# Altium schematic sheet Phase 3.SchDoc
size Tabloid; SheetNumber: 5; SheetTotal: 7
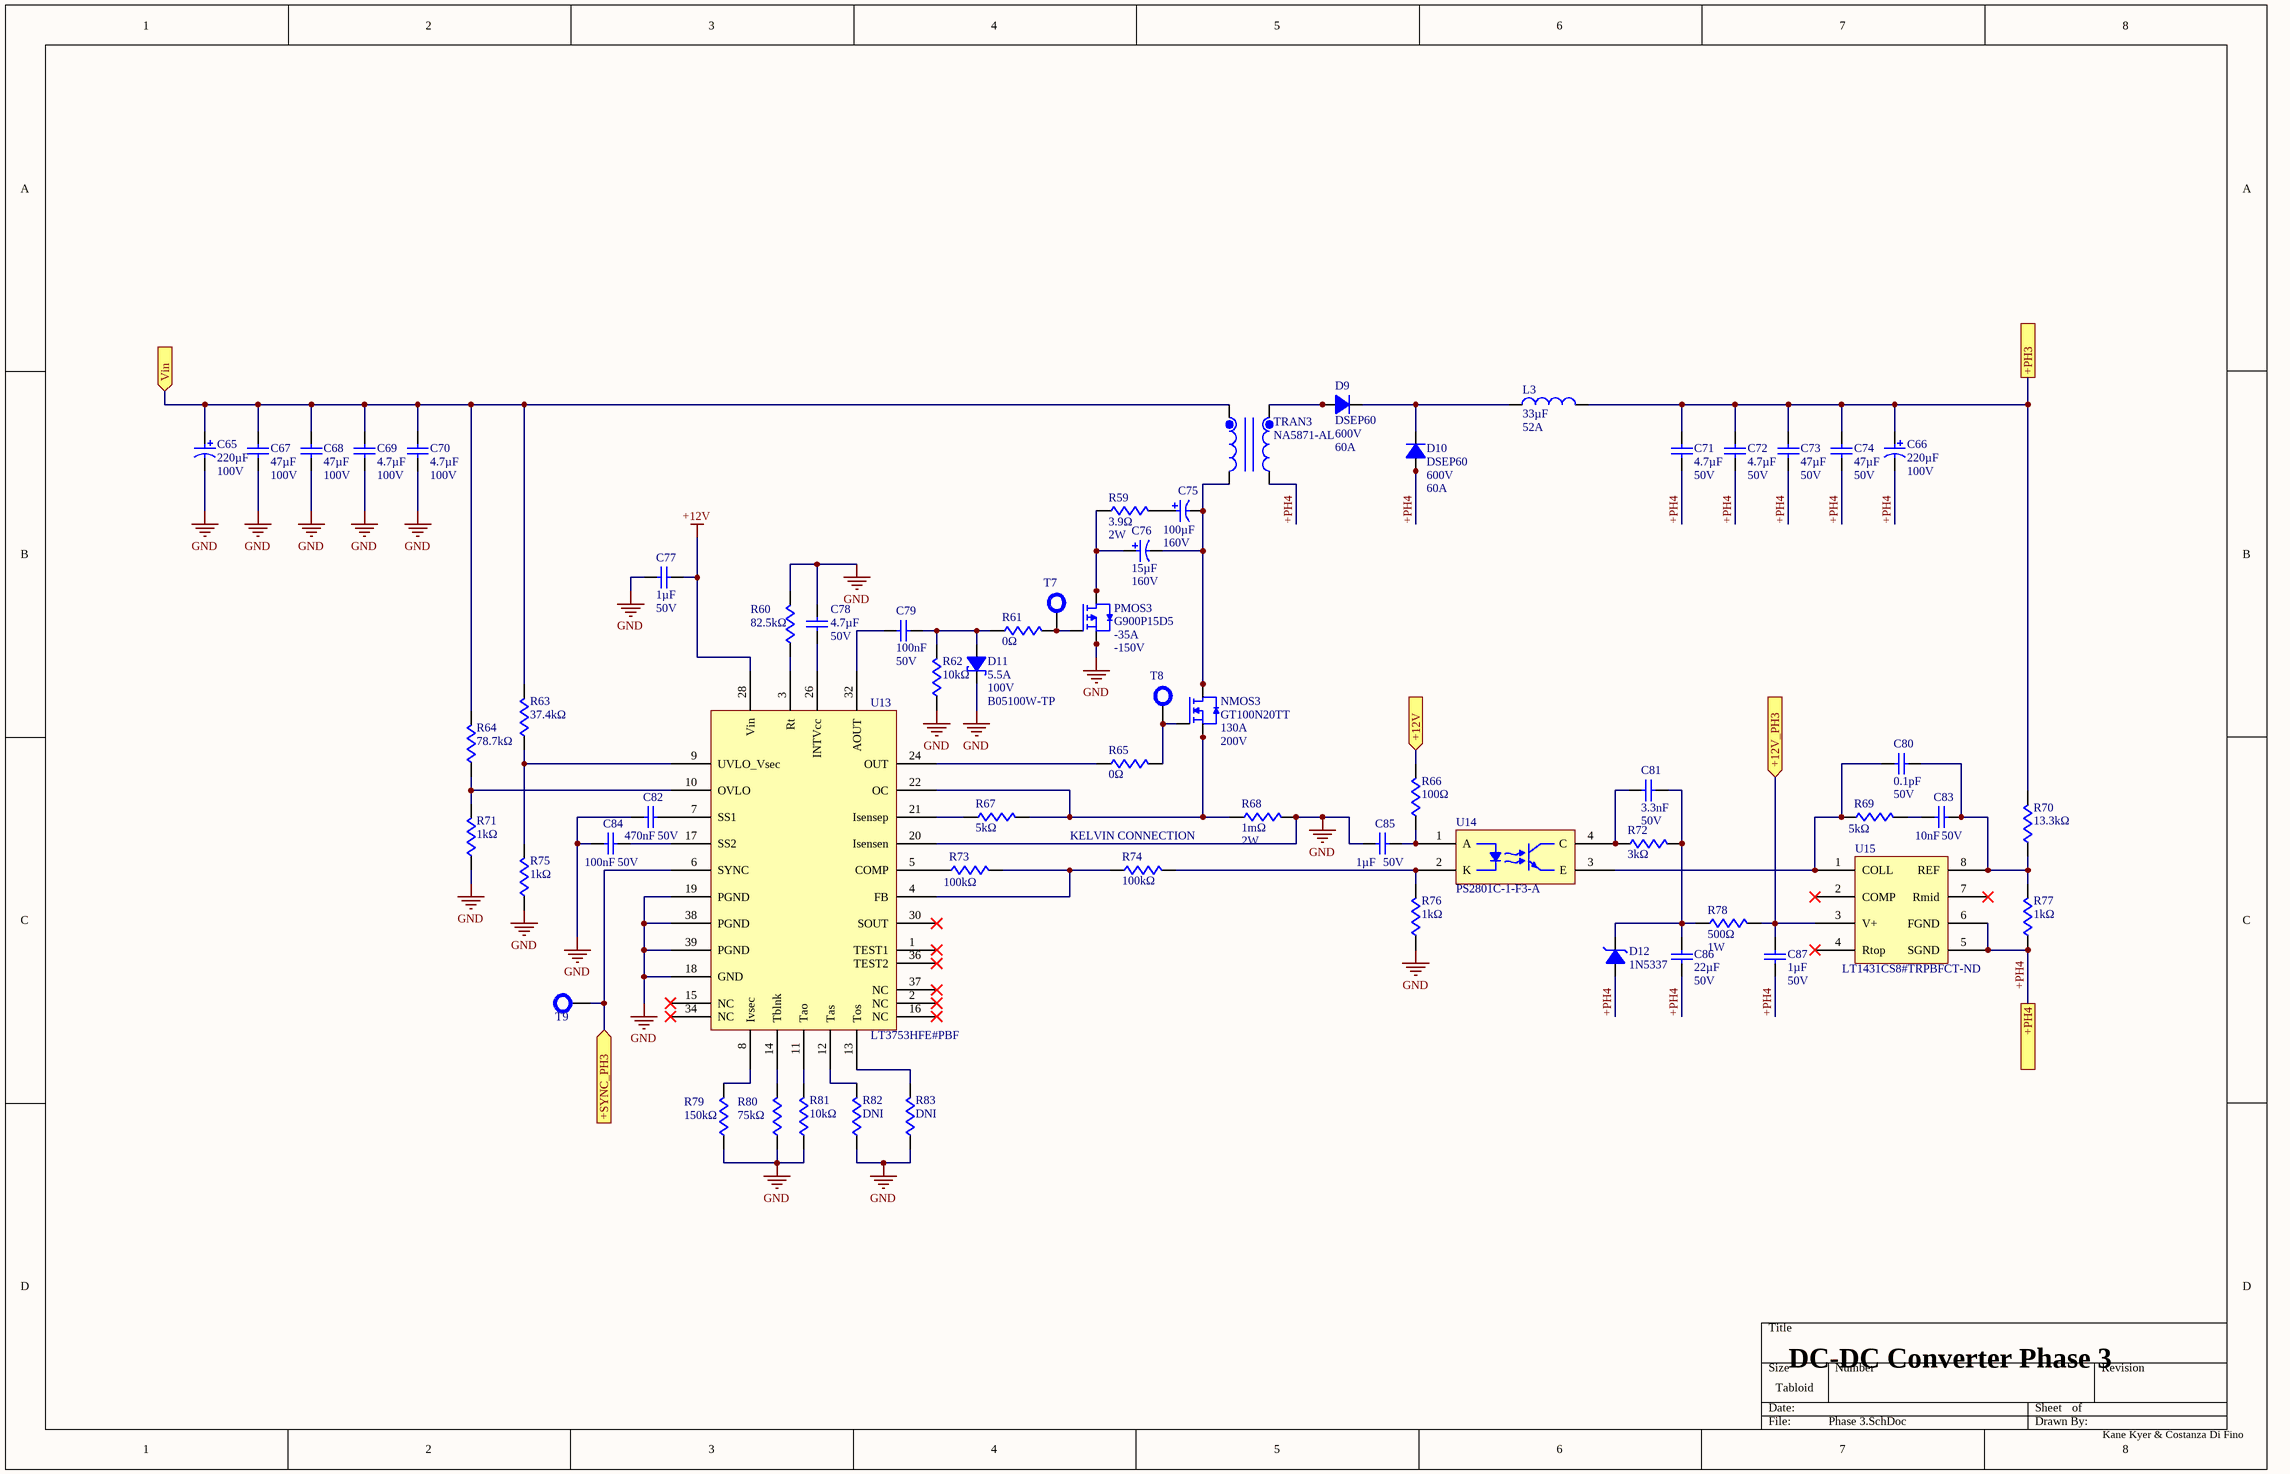
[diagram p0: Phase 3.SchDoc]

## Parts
C65  value 220µF  Voltage Rating: 100V  [C_AEC]  (hidden comment: AFK227M2AR44T-F)
C66  value 220µF  Voltage Rating: 100V  [C_AEC]  (hidden comment: AFK227M2AR44T-F)
C67  value 47µF  Voltage Rating: 100V  [C_CAA573]  (hidden comment: CAA573X7S2A476M640LH)
C68  value 47µF  Voltage Rating: 100V  [C_CAA573]  (hidden comment: CAA573X7S2A476M640LH)
C69  value 4.7µF  Voltage Rating (DC): 100V  [C_1210]  (hidden comment: GMC32X7S475K100NT)
C70  value 4.7µF  Voltage Rating (DC): 100V  [C_1210]  (hidden comment: GMC32X7S475K100NT)
C71  value 4.7µF  Voltage Rating (DC): 50V  [C_1206]  (hidden comment: GMC31X7R475K50NT)
C72  value 4.7µF  Voltage Rating (DC): 50V  [C_1206]  (hidden comment: GMC31X7R475K50NT)
C73  value 47µF  Voltage Rating (DC): 50V  [C_CKG57N]  (hidden comment: CKG57NX7R1H476M500JJ)
C74  value 47µF  Voltage Rating (DC): 50V  [C_CKG57N]  (hidden comment: CKG57NX7R1H476M500JJ)
C75  value 100µF  Voltage Rating (DC): 160V  [UUJ2C101MNJ1MS]  (hidden comment: UUJ2C101MNJ1MS)
C76  value 15µF  Voltage: 160V  [ULT2C150MNL1GS]  (hidden comment: ULT2C150MNL1GS)
C77  value 1µF  Voltage: 50V  [C_0805]  (hidden comment: CL21B105KBFNNNE)
C78  value 4.7µF  Voltage Rating (DC): 50V  [C_1206]  (hidden comment: GMC31X7R475K50NT)
C79  value 100nF  Voltage Rating: 50V  [C_0603]  (hidden comment: C0603C104K5RACTU)
C80  value 0.1pF  Voltage Rating: 50V  [C_0402]  (hidden comment: GJM1555C1HR10WB01D)
C81  value 3.3nF  Voltage Rating: 50V  [C_0603]  (hidden comment: GCM1885C1H332FA16D)
C82  value 470nF  Voltage Rating: 50V  [C_0402]  (hidden comment: GRM155R61H474KE11D)
C83  value 10nF  Voltage Rating: 50V  [C_0603]  (hidden comment: C0603C103K5RACTU)
C84  value 100nF  Voltage Rating: 50V  [C_0603]  (hidden comment: C0603C104K5RACTU)
C85  value 1µF  Voltage: 50V  [C_0805]  (hidden comment: CL21B105KBFNNNE)
C86  value 22µF  Voltage Rating (DC): 50V  [C_2220]  (hidden comment: GMC55X7R226M50NT)
C87  value 1µF  Voltage: 50V  [C_0805]  (hidden comment: CL21B105KBFNNNE)
D9  DSEP60  Vr: 600V  Io: 60A  [D_DSEP60]
D10  DSEP60  Vr: 600V  Io: 60A  [D_DSEP60]
D11  Max Forward Surge Current (Ifsm): 5.5A  Min Breakdown Voltage: 100V  [D_B05100W]  (hidden comment: B05100W-TP)
D12  Supplier Part Number: 1N5337  [D_1N5337]  (hidden comment: 1N5337BRLG)
L3  value 33µF  Irms: 52A  [CPEX4141L-330MC]  (hidden comment: CPEX4141L-330MC)
NMOS3  Id: 130A  Vds: 200V  [GT100N20TT]  (hidden comment: GT100N20TT)
PMOS3  Id: -35A  Vds: -150V  [G900P15]  (hidden comment: G900P15D5)
R59  value 3.9Ω  Power Rating: 2W  [R_SM2W]  (hidden comment: SMW23R9JT)
R60  value 82.5kΩ  [R_0805]  (hidden comment: RMCF0805FT82K5)
R61  value 0Ω  [R_0805]  (hidden comment: CRCW08050000Z0EA)
R62  value 10kΩ  [R_0402]  (hidden comment: RM04F1002CT)
R63  value 37.4kΩ  [R_0603]  (hidden comment: RC0603FR-0737K4L)
R64  value 78.7kΩ  [R_0603]  (hidden comment: RC0603FR-0778K7L)
R65  value 0Ω  [R_0805]  (hidden comment: CRCW08050000Z0EA)
R66  value 100Ω  [R_0603]  (hidden comment: RC0603FR-07100RL)
R67  value 5kΩ  [R_0402]  (hidden comment: PNM0402E5001BST1)
R68  value 1mΩ  Power Rating: 2W  [R_2512]  (hidden comment: CRE2512-FZ-R001E-2)
R69  value 5kΩ  [R_0402]  (hidden comment: PNM0402E5001BST1)
R70  value 13.3kΩ  [R_0603]  (hidden comment: RMCF0603FT13K3)
R71  value 1kΩ  [R_0402]  (hidden comment: RM04F1001CT)
R72  value 3kΩ  [C_0402]  (hidden comment: AC0402FR-073KL)
R73  value 100kΩ  [R_0402]  (hidden comment: RM04F1003CT)
R74  value 100kΩ  [R_0402]  (hidden comment: RM04F1003CT)
R75  value 1kΩ  [R_0402]  (hidden comment: RM04F1001CT)
R76  value 1kΩ  [R_0402]  (hidden comment: RM04F1001CT)
R77  value 1kΩ  [R_0402]  (hidden comment: RM04F1001CT)
R78  value 500Ω  Power Rating: 1W  [R_WSC2515]  (hidden comment: WSC2515500R0FEB)
R79  value 150kΩ  [R_0603]  (hidden comment: RC0603FR-07150KL)
R80  value 75kΩ  [R_0603]  (hidden comment: AC0603FR-0775KL)
R81  value 10kΩ  [R_0402]  (hidden comment: RM04F1002CT)
R82  value DNI  [R_0805]  (hidden comment: CRCW08050000Z0EA)
R83  value DNI  [R_0805]  (hidden comment: CRCW08050000Z0EA)
T7  TEST  [TEST_POINT]  (value not drawn)
T8  TEST  [TEST_POINT]  (value not drawn)
T9  TEST  [TEST_POINT]  (value not drawn)
TRAN3  NA5871-AL  [NA5871-AL]
U13  LT3753HFE#PBF  [LT3753]
U14  PS2801C-1-F3-A  [PS2801C]
U15  Supplier Part Number: LT1431CS8#TRPBFCT-ND  [LT1431]  (hidden comment: LT1431CS8#TRPBF)

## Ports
+12V (in, see SHEET_MAP[4C], Externals[2A], Phase 1[4C], Phase 2[4C], Phase 4[4C], Phase 5[4B]), +12V_PH3 (in, see SHEET_MAP[4C], Externals[6B]), +PH3 (see SHEET_MAP[4B], Externals[4C], Phase 2[6C]), +PH4 (see SHEET_MAP[4C], Externals[6B], Phase 4[6B]), +SYNC_PH3 (in, see SHEET_MAP[4C], Externals[3C]), Vin (in, see SHEET_MAP[4B], Externals[1A], Phase 1[1B], Phase 2[1B], Phase 4[1B], Phase 5[1B])

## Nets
+12V: C77.2 U13.28(Vin)
GND: C65.2 C67.1 C68.1 C69.1 C70.1 C77.1 C78.1 C82.1 C84.1 C85.1 D11.1 PMOS3.1(S) PMOS3.2(S) PMOS3.3(S) R60.2 R62.1 R68.2 R71.1 R75.1 R76.1 R79.1 R80.1 R81.1 R82.1 R83.1 U13.18(GND) U13.19(PGND) U13.20(Isensen) U13.38(PGND) U13.39(PGND)
+12V: R66.2 ; port +12V  [a separate net that carries the same name]
+12V_PH3: C87.2 R78.2 U15.3(V+) ; port +12V_PH3
+PH3: C66.1 C71.2 C72.2 C73.2 C74.2 L3.2 R70.2 ; port +PH3
+PH4: C66.2 C71.1 C72.1 C73.1 C74.1 C86.1 C87.1 D10.1(A) D10.3(A) D12.2 R77.1 TRAN3.11 U15.5(SGND) U15.6(FGND) ; port +PH4
+SYNC_PH3: T9.1 U13.6(SYNC) ; port +SYNC_PH3
Vin: C65.1 C67.2 C68.2 C69.2 C70.2 R63.2 R64.2 TRAN3.1 ; port Vin
NetC75_1: C75.1 R59.2
NetC75_2: C75.2 C76.2 NMOS3.9(D) NMOS3.10(D) NMOS3.11(D) NMOS3.12(D) NMOS3.13(D) NMOS3.14(D) NMOS3.15(D) NMOS3.16(D) TRAN3.4
NetC76_1: C76.1 PMOS3.5(D) PMOS3.6(D) PMOS3.7(D) PMOS3.8(D) R59.1
NetC78_2: C78.2 U13.26(INTVcc)
NetC79_1: C79.1 U13.32(AOUT)
NetC79_2: C79.2 D11.2 R61.1 R62.2
NetC80_1: C80.1 R69.1 U14.3(E) U15.1(COLL)
NetC80_2: C80.2 C83.2 R70.1 R77.2 U15.8(REF)
NetC81_1: C81.1 R72.1 U14.4(C)
NetC81_2: C81.2 C86.2 D12.1 R72.2 R78.1
NetC82_2: C82.2 U13.7(SS1)
NetC83_1: C83.1 R69.2
NetC84_2: C84.2 U13.17(SS2)
NetC85_2: C85.2 R66.1 U14.1(A)
NetD9_1: D9.1(A) D9.3(A) TRAN3.6
NetD9_4: D9.4(C) D10.4(C) L3.1
NetNMOS3_1: NMOS3.1(S) NMOS3.2(S) NMOS3.3(S) NMOS3.4(S) NMOS3.5(S) NMOS3.6(S) NMOS3.7(S) R67.2 R68.1 U13.22(OC)
NetNMOS3_8: NMOS3.8(G) R65.2 T8.1
NetPMOS3_4: PMOS3.4(G) R61.2 T7.1
NetR60_1: R60.1 U13.3(Rt)
NetR63_1: R63.1 R75.2 U13.9(UVLO_Vsec)
NetR64_1: R64.1 R71.2 U13.10(OVLO)
NetR65_1: R65.1 U13.24(OUT)
NetR67_1: R67.1 U13.21(Isensep)
NetR73_1: R73.1 U13.5(COMP)
NetR73_2: R73.2 R74.1 U13.4(FB)
NetR74_2: R74.2 R76.2 U14.2(K)
NetR79_2: R79.2 U13.8(Ivsec)
NetR80_2: R80.2 U13.14(Tblnk)
NetR81_2: R81.2 U13.11(Tao)
NetR82_2: R82.2 U13.12(Tas)
NetR83_2: R83.2 U13.13(Tos)

Not connected (* = marked no-connect by the designer): U13 1(TEST1)* 2(NC)* 15(NC)* 16(NC)* 30(SOUT)* 34(NC)* 36(TEST2)* 37(NC)*; U15 2(COMP)* 4(Rtop)* 7(Rmid)*

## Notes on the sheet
- (near R74) KELVIN CONNECTION
- DC-DC Converter Phase 3
- Kane Kyer & Costanza Di Fino

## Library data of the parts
C65 C66 = AFK227M2AR44T-F: Radial Can - SMD ALUMINUM ELECTROLYTIC CAPACITOR AFK 100V 220muF ±20% 0.709Dia 18.00mm; Manufacturer: Cornell Dubilier; Dissipation Factor: 0.07%; ESR (Equivalent Series Resistance): 150mΩ; Leakage Current: 220µA; Life (Hours): 5000hours; Ripple Current: 687.75mA; Ripple Current (AC): 917mA
C67 C68 = CAA573X7S2A476M640LH: Multilayer Ceramic Chip Capacitors, Capacitance=47μF, LxWxT: 6.0x7.5x6.4mm; Manufacturer: TDK; Manufacturer Lifecycle Status: PRODUCTION; Tolerance: 20%
C69 C70 = GMC32X7S475K100NT: Ceramic Capacitor, Multilayer, Ceramic, 100V, 10% +Tol, 10% -Tol, X7S, 22% TC, 4.7uF, Surface Mount, 1210; Manufacturer: Cal-Chip Electronics
C71 C72 C78 = GMC31X7R475K50NT: Ceramic Capacitor, Multilayer, Ceramic, 50V, 10% +Tol, 10% -Tol, X7R, 15% TC, 4.7uF, Surface Mount, 1206; Manufacturer: Cal-Chip Electronics
C73 C74 = CKG57NX7R1H476M500JJ: Ceramic Capacitor, Multilayer, Ceramic, 50V, 20% +Tol, 20% -Tol, X7R, 15% TC, 47uF, Surface Mount, 2420; Manufacturer: TDK; Manufacturer Lifecycle Status: PRODUCTION
C75 = UUJ2C101MNJ1MS: Aluminum Electrolytic Capacitors 100 F 160 V Radial, SMD 5000 Hrs 105C; Manufacturer: Nichicon; Leakage Current: 740µA; Ripple Current: 380mA
C76 = ULT2C150MNL1GS: Radial Can - SMD ALUMINUM ELECTROLYTIC CAPACITOR ULT 160V 15muF ±20% 0.315Dia 8.00mm; Manufacturer: Nichicon; Leakage Current: 196µA; Life (Hours): 2000hours; Polarity: Polar; Ripple Current: 45mA
C77 C85 C87 = CL21B105KBFNNNE: 50V 1uF X7R ±10% 0805 Multilayer Ceramic Capacitors MLCC - SMD/SMT ROHS; Manufacturer: Samsung Electro-Mechanics
C79 C84 = C0603C104K5RACTU: 50V 100nF X7R ±10% 0603 Multilayer Ceramic Capacitors MLCC - SMD/SMT ROHS; Manufacturer: KEMET; Dissipation Factor: 2.5%; Temperature Coefficient: 30ppm/°C
C80 = GJM1555C1HR10WB01D: Multilayer Ceramic Capacitor, 0.1 pF, 50 V, ± 0.05pF, C0G (NP0), 0402 [1005 Metric]; Manufacturer: Murata; Manufacturer Lifecycle Status: IN PRODUCTION; Temperature Coefficient: 30ppm/°C
C81 = GCM1885C1H332FA16D: 50V 3.3nF C0G ±1% 0603 Multilayer Ceramic Capacitors MLCC - SMD/SMT ROHS; Manufacturer: Murata; Manufacturer Lifecycle Status: IN PRODUCTION; Temperature Coefficient: 30ppm/°C
C82 = GRM155R61H474KE11D: 50V 470nF X5R ±10% 0402 Multilayer Ceramic Capacitors MLCC - SMD/SMT ROHS; Manufacturer: Murata; Manufacturer Lifecycle Status: IN PRODUCTION
C83 = C0603C103K5RACTU: Capacitor, Multilayer, Ceramic, 50V, 10%, X7R, 15% Tc, 0.01Uf, Surface Mount, 0603; Manufacturer: KEMET; Dissipation Factor: 2.5%; Temperature Coefficient: 30ppm/°C
C86 = GMC55X7R226M50NT: Ceramic Capacitor, Multilayer, Ceramic, 50V, 20% +Tol, 20% -Tol, X7R, 15% TC, 22uF, Surface Mount, 2220; Manufacturer: Cal-Chip Electronics
D9 D10 = DSEP60-06AZ-TRL: Power Diode Discretes-FRED TO-; Manufacturer: IXYS
D11 = B05100W-TP: Rectifier Diode, Schottky, 1 Phase, 1 Element, 0.5A, 100V V(RRM), Silicon; Manufacturer: MCC; Forward Voltage: 850mV; Max Output current: 500mA; Number of Elements: 1; Peak Reverse Current: 1µA
D12 = 1N5337BRLG: Zener Diode Single 4.7V 5% 2Ohm 5000mW 2-Pin Case 017AA-01 T/R / DIODE ZENER 4.7V 5W AXIAL; Manufacturer: onsemi; Manufacturer Lifecycle Status: ACTIVE; Forward Voltage: 1.2V; Impedance: 2Ω; Max Reverse Leakage Current: 5µA; Number of Elements: 1; Polarity: Unidirectional; Test Current: 260mA
L3 = CPEX4141L-330MC: Fixed Ind 33UH 52A 1.88 Mohm Th; Manufacturer: Codaca
NMOS3 = GT100N20TT: Mosfet N-ch 200V 130A 280W Tolt; Manufacturer: GoFord
PMOS3 = G900P15D5: P-150V, -60A, RD(max) Less Than 80mOhm at -10V, VTH -1V to -4V, DFN5x6-8L; Manufacturer: GoFord; Manufacturer Lifecycle Status: ACTIVE
R59 = SMW23R9JT: SM Series 3.9 Ohm ±5 % 2 W ±200 ppm/°C Surface Mount Wirewound Resistor; Manufacturer: TE Connectivity; Manufacturer Lifecycle Status: ACTIVE; Insulation Resistance: 10GΩ; Number of Resistors: 1; Operating Supply Voltage: 300V; Tolerance: 5%
R60 = RMCF0805FT82K5: Res Thick Film 0805 82.5K Ohm 1% 1/8W ±100ppm/°C Molded SMD SMD Paper T/R; Manufacturer: Stackpole Electronics; Max Power Dissipation: 125mW; Voltage Rating: 150V
R61 R65 R82 R83 = CRCW08050000Z0EA: Zero Ohm Resistor, Jumper, 0805 [2012 Metric], Thick Film, 125 mW, 2.5 A, Surface Mount Device; Manufacturer: Vishay; Manufacturer Package Identifier: CRCW0805-e3; Power Dissipation: 125mW; Temperature Coefficient: 100ppm/°C; Tolerance: 1%; Voltage Rating: 150V
R62 R81 = RM04F1002CT: Fixed Resistor, Metal Glaze/thick Film, 0.0625W, 10000ohm, 50V, 1% +/-Tol, Surface Mount, 0402; Manufacturer: Cal-Chip Electronics; Power Dissipation: 62.5mW; Power Rating: 63mW; Temperature Coefficient: 100ppm/°C
R63 = RC0603FR-0737K4L: 100mW Thick Film Resistors 75V ±100ppm/℃ ±1% 37.4kΩ 0603 Chip Resistor - Surface Mount ROHS; Manufacturer: Yageo Group; Temperature Coefficient: 100ppm/°C; Voltage Rating (DC): 50V
R64 = RC0603FR-0778K7L: Res Thick Film 0603 78.7K Ohm 1% 0.1W(1/10W) ±100ppm/C Pad SMD T/R; Manufacturer: Yageo Group; Power Dissipation: 100mW; Temperature Coefficient: 100ppm/°C; Voltage Rating: 75V; Voltage Rating (DC): 50V
R66 = RC0603FR-07100RL: Yageo RC0603FR-07100RL 0603 SMD Resistor 100 Ohm thin film chip resistor; Manufacturer: Yageo Group; Power Dissipation: 100mW; Temperature Coefficient: 100ppm/°C; Tolerance: 1%; Voltage Rating: 75V; Voltage Rating (DC): 50V
R67 R69 = PNM0402E5001BST1: Res Thin Film 0402 5K Ohm 0.1% 0.05W(1/20W) +/-25ppm/C Sulfur Resistant Pad SMD Medical T/R; Manufacturer: Vishay; Power Dissipation: 50mW; Temperature Coefficient: 25ppm/°C; Working Voltage: 75V
R68 = CRE2512-FZ-R001E-2: Res Thick Film 2512 1m Ohm 1% 2W ±75ppm/°C Molded SMD Embossed T/R; Manufacturer: Bourns; Temperature Coefficient: 50ppm/°C
R70 = RMCF0603FT13K3: Res Thick Film 0603 13.3K Ohm 1% 0.1W(1/10W) ±100ppm/C Pad SMD Automotive T/R; Manufacturer: Stackpole Electronics; Power Dissipation: 100mW; Temperature Coefficient: 100ppm/°C; Voltage Rating: 75V
R71 R75-R77 = RM04F1001CT: 62.5mW Thick Film Resistors ±100ppm/℃ ±1% 1kΩ 0402 Chip Resistor - Surface Mount ROHS; Manufacturer: Cal-Chip Electronics; Temperature Coefficient: 100ppm/°C; Working Voltage: 50V
R72 = AC0402FR-073KL: Res Thick Film 0402 3K Ohm 1% 0.063W(1/16W) ±100ppm/C Pad SMD Automotive T/R; Manufacturer: Yageo Group; Max Power Dissipation: 63mW; Power Dissipation: 62.5mW; Temperature Coefficient: 100ppm/°C; Voltage Rating: 50V
R73 R74 = RM04F1003CT: Fixed Resistor, Metal Glaze/thick Film, 0.0625W, 100000ohm, 50V, 1% +/-Tol, Surface Mount, 0402; Manufacturer: Cal-Chip Electronics; Power Dissipation: 62.5mW; Temperature Coefficient: 100ppm/°C
R78 = WSC2515500R0FEB: Fixed Resistor, Wire Wound, 1W, 500ohm, 22.3607V, 1% +/-Tol, 20ppm/Cel, Surface Mount, 2515; Manufacturer: Vishay; Temperature Coefficient: 20ppm/°C
R79 = RC0603FR-07150KL: 100mW Thick Film Resistors 75V ±100ppm/℃ ±1% 150kΩ 0603 Chip Resistor - Surface Mount ROHS; Manufacturer: Yageo Group; Temperature Coefficient: 100ppm/°C; Voltage Rating (AC): 50V
R80 = AC0603FR-0775KL: Res Thick Film 0603 75K Ohm 1% 0.1W(1/10W) ±100ppm/C Pad SMD T/R Automotive AEC-Q200; Manufacturer: Yageo Group; Max Power Dissipation: 100mW; Temperature Coefficient: 100ppm/°C; Voltage Rating: 75V
TRAN3 = NA5871-AL: Transformer, planar, for TI UCC28950, SMT, RoHS; Manufacturer: Coilcraft; Max Supply Voltage: 60V; Min Input Voltage: 38V; Power Rating: 800W
U13 = LT3753HFE#PBF: 500kHz 8.5V~100V Buck-boost type 1 TSSOP-38-EP-4.4mm DC-DC Controllers ROHS; Manufacturer: Analog Devices; Manufacturer Lifecycle Status: PRODUCTION; Clock Sync: Yes; Max Supply Voltage: 100V; Min Supply Voltage: 8.5V; Nominal Supply Voltage: 12V; Number of Output Phases: 1; Topology: Forward Converter
U14 = PS2801C-1-F3-A: Optocoupler DC-IN 1-CH Transistor DC-OUT 4-Pin SSOP T/R; Manufacturer: Renesas; Manufacturer Lifecycle Status: ACTIVE; Collector Emitter Breakdown Voltage: 80V; Collector Emitter Saturation Voltage: 300mV; Current Transfer Ratio: 50%; Dark Current: 100nA; Forward Current: 30mA; Forward Voltage: 1.4V; Input Current: 5mA; Isolation Voltage: 2.5kV; Max Power Dissipation: 120mW; Number of Elements: 1; Reverse Breakdown Voltage: 6V; Target Application: PLC\, Hybrid IC\, Power supply\, OA\, Measuring instrument\, Modem\, Communication devices
U15 = LT1431CS8#TRPBF: V-Ref Adjustable 2.5V to 36V 100mA 8-Pin SOIC N T/R; Manufacturer: Analog Devices; Manufacturer Lifecycle Status: PRODUCTION; Cathode Current: 1mA; Reference Type: Shunt; Temperature Coefficient: 30ppm/°C; Tolerance: 0.4%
